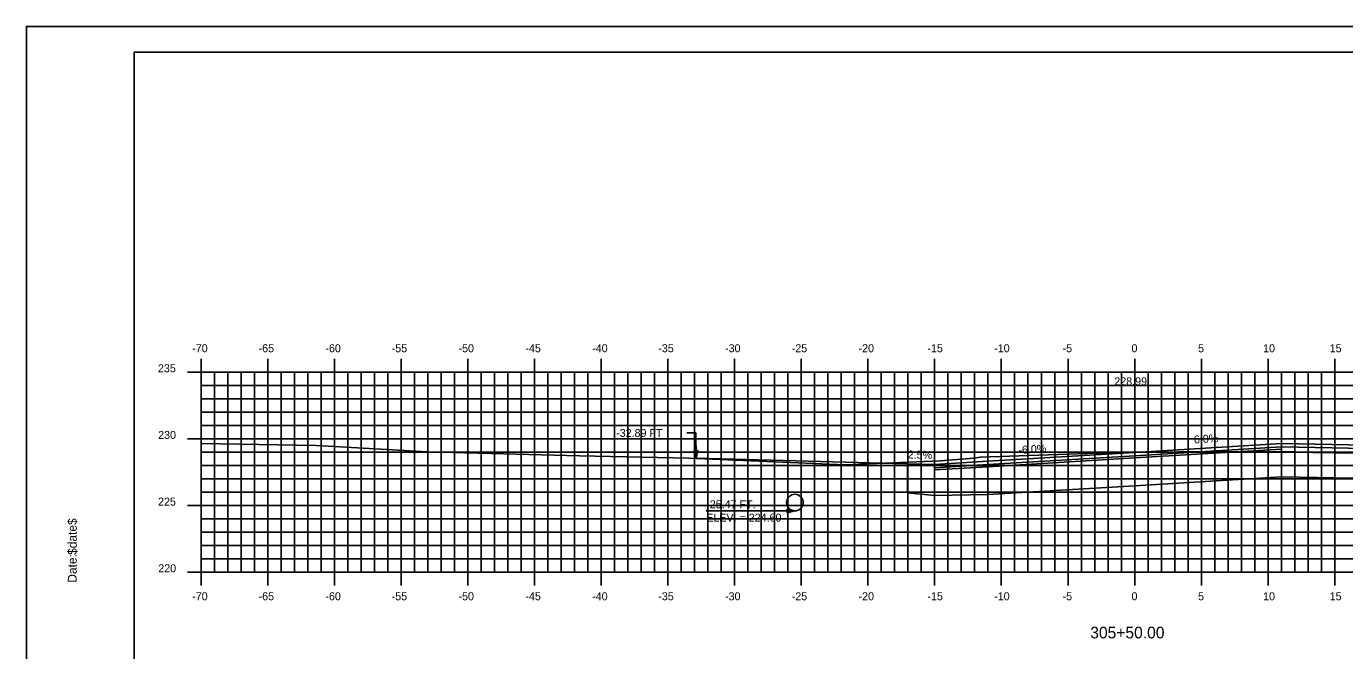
# Model space of a CAD drawing. Extents: x 1137211 to 1137381, y 608981 to 609091.
# Drawn here: x 1137210.8 to 1137309.6, y 609044.5 to 609091.3 of the extents above; entities that cross this region are included whole.
import ezdxf

# ---------------------------------------------------------------- set-up
doc = ezdxf.new("R2010")
doc.units = 0
for name, color, linetype in [('ANNOTATION', 7, 'Continuous'), ('BORDER', 7, 'Continuous'), ('D_Drainage_Culvert', 7, 'Continuous'), ('D_Roadway_Centerline', 7, 'Continuous'), ('D_Roadway_Centerline_Text', 7, 'Continuous'), ('D_Roadway_Edge_Shoulder', 7, 'Continuous'), ('D_Roadway_Edge_TW', 7, 'Continuous'), ('D_Roadway_Pavement', 7, 'Continuous'), ('D_Roadway_SubGrade', 7, 'Continuous'), ('D_Text_Standard', 7, 'Continuous'), ('H_V ANNOTATION', 7, 'Continuous'), ('MAJOR', 7, 'Continuous'), ('MINOR', 7, 'Continuous'), ('PLOT BOUNDARY', 7, 'Continuous'), ('S_Roadway_Centerline', 7, 'Continuous')]:
    doc.layers.add(name, color=color, linetype=linetype)

msp = doc.modelspace()

# ---------------------------------------------------------------- linework, layer by layer
at = {"layer": 'ANNOTATION'}
msp.add_line((1137276.858, 609058.474), (1137261.006, 609058.882), dxfattribs=at)
at = {"layer": 'BORDER'}
msp.add_lwpolyline([(1137218.897, 608984.335), (1137378.897, 608984.335), (1137378.897, 609089.335), (1137218.897, 609089.335)], close=True, dxfattribs=at)
at = {"layer": 'D_Drainage_Culvert'}
msp.add_circle((1137268.426, 609055.558), 0.625, dxfattribs=at)
at = {"layer": 'D_Roadway_Edge_Shoulder'}
for points in [[(1137304.896, 609059.983), (1137326.284, 609059.555), (1137326.284, 609059.305), (1137304.896, 609059.733)], [(1137282.896, 609058.663), (1137278.896, 609058.423), (1137278.896, 609058.173), (1137282.896, 609058.413)]]:
    msp.add_lwpolyline(points, close=True, dxfattribs=at)
at = {"layer": 'D_Roadway_Edge_TW'}
for points in [[(1137282.896, 609058.413), (1137282.896, 609058.663), (1137293.896, 609059.323), (1137304.896, 609059.983), (1137304.896, 609059.733), (1137293.896, 609059.073)], [(1137282.896, 609058.246), (1137278.896, 609058.006), (1137278.896, 609058.173), (1137282.896, 609058.413)]]:
    msp.add_lwpolyline(points, close=True, dxfattribs=at)
at = {"layer": 'D_Roadway_Pavement'}
msp.add_lwpolyline([(1137282.896, 609058.246), (1137282.896, 609058.413), (1137293.896, 609059.073), (1137304.896, 609059.733), (1137304.896, 609059.566), (1137293.896, 609058.906)], close=True, dxfattribs=at)
at = {"layer": 'D_Roadway_SubGrade'}
for points in [[(1137282.896, 609056.163), (1137282.896, 609058.246), (1137293.896, 609058.906), (1137304.896, 609059.566), (1137304.896, 609057.483), (1137293.896, 609056.823)], [(1137304.896, 609059.566), (1137304.896, 609059.733), (1137326.284, 609059.305), (1137326.284, 609059.555), (1137326.284, 609059.555), (1137335.681, 609056.925), (1137304.896, 609057.483)], [(1137276.858, 609056.289), (1137278.896, 609056.083), (1137282.896, 609056.163), (1137282.896, 609058.246), (1137282.896, 609058.413), (1137278.896, 609058.173), (1137278.896, 609058.423), (1137276.858, 609058.474)]]:
    msp.add_lwpolyline(points, close=True, dxfattribs=at)
at = {"layer": 'D_Text_Standard'}
msp.add_line((1137261.77, 609054.933), (1137266.367, 609054.933), dxfattribs=at)
for points in [[(1137261.006, 609058.882), (1137261.002, 609060.781), (1137260.322, 609060.781)], [(1137268.426, 609054.933), (1137267.047, 609054.933), (1137266.367, 609054.933)]]:
    msp.add_lwpolyline(points, dxfattribs=at)
for points in [[(1137261.006, 609058.882), (1137260.859, 609059.464), (1137261.15, 609059.464)], [(1137268.426, 609054.933), (1137267.844, 609054.787), (1137267.844, 609055.078)]]:
    msp.add_lwpolyline(points, close=True, dxfattribs=at)
at = {"layer": 'MAJOR'}
for p, q in [((1137223.896, 609066.337), (1137223.896, 609065.335)), ((1137228.896, 609066.337), (1137228.896, 609065.335)), ((1137233.896, 609066.337), (1137233.896, 609065.335)), ((1137238.896, 609066.337), (1137238.896, 609065.335)), ((1137243.896, 609066.337), (1137243.896, 609065.335)), ((1137248.896, 609066.337), (1137248.896, 609065.335)), ((1137253.896, 609066.337), (1137253.896, 609065.335)), ((1137258.896, 609066.337), (1137258.896, 609065.335)), ((1137263.896, 609066.337), (1137263.896, 609065.335)), ((1137268.896, 609066.337), (1137268.896, 609065.335)), ((1137273.896, 609066.337), (1137273.896, 609065.335)), ((1137278.896, 609066.337), (1137278.896, 609065.335)), ((1137283.896, 609066.337), (1137283.896, 609065.335)), ((1137288.896, 609066.337), (1137288.896, 609065.335)), ((1137293.896, 609066.337), (1137293.896, 609065.335)), ((1137298.896, 609066.337), (1137298.896, 609065.335)), ((1137303.896, 609066.337), (1137303.896, 609065.335)), ((1137308.896, 609066.337), (1137308.896, 609065.335)), ((1137222.894, 609065.335), (1137223.896, 609065.335)), ((1137223.896, 609065.335), (1137363.896, 609065.335)), ((1137223.896, 609050.335), (1137223.896, 609065.335)), ((1137223.896, 609050.335), (1137223.896, 609065.335)), ((1137223.896, 609065.335), (1137363.896, 609065.335)), ((1137228.896, 609050.335), (1137228.896, 609065.335)), ((1137233.896, 609050.335), (1137233.896, 609065.335)), ((1137238.896, 609050.335), (1137238.896, 609065.335)), ((1137243.896, 609050.335), (1137243.896, 609065.335)), ((1137248.896, 609050.335), (1137248.896, 609065.335)), ((1137253.896, 609050.335), (1137253.896, 609065.335)), ((1137258.896, 609050.335), (1137258.896, 609065.335)), ((1137263.896, 609050.335), (1137263.896, 609065.335)), ((1137268.896, 609050.335), (1137268.896, 609065.335)), ((1137273.896, 609050.335), (1137273.896, 609065.335)), ((1137278.896, 609050.335), (1137278.896, 609065.335)), ((1137283.896, 609050.335), (1137283.896, 609065.335)), ((1137288.896, 609050.335), (1137288.896, 609065.335)), ((1137293.896, 609050.335), (1137293.896, 609065.335)), ((1137298.896, 609050.335), (1137298.896, 609065.335)), ((1137303.896, 609050.335), (1137303.896, 609065.335)), ((1137308.896, 609050.335), (1137308.896, 609065.335)), ((1137222.894, 609060.335), (1137223.896, 609060.335)), ((1137223.896, 609060.335), (1137363.896, 609060.335)), ((1137222.894, 609055.335), (1137223.896, 609055.335)), ((1137223.896, 609055.335), (1137363.896, 609055.335)), ((1137222.894, 609050.335), (1137223.896, 609050.335)), ((1137223.896, 609050.335), (1137363.896, 609050.335)), ((1137223.896, 609050.335), (1137363.896, 609050.335)), ((1137223.896, 609049.333), (1137223.896, 609050.335)), ((1137228.896, 609049.333), (1137228.896, 609050.335)), ((1137233.896, 609049.333), (1137233.896, 609050.335)), ((1137238.896, 609049.333), (1137238.896, 609050.335)), ((1137243.896, 609049.333), (1137243.896, 609050.335)), ((1137248.896, 609049.333), (1137248.896, 609050.335)), ((1137253.896, 609049.333), (1137253.896, 609050.335)), ((1137258.896, 609049.333), (1137258.896, 609050.335)), ((1137263.896, 609049.333), (1137263.896, 609050.335)), ((1137268.896, 609049.333), (1137268.896, 609050.335)), ((1137273.896, 609049.333), (1137273.896, 609050.335)), ((1137278.896, 609049.333), (1137278.896, 609050.335)), ((1137283.896, 609049.333), (1137283.896, 609050.335)), ((1137288.896, 609049.333), (1137288.896, 609050.335)), ((1137293.896, 609049.333), (1137293.896, 609050.335)), ((1137298.896, 609049.333), (1137298.896, 609050.335)), ((1137303.896, 609049.333), (1137303.896, 609050.335)), ((1137308.896, 609049.333), (1137308.896, 609050.335))]:
    msp.add_line(p, q, dxfattribs=at)
at = {"layer": 'MINOR'}
for p, q in [((1137224.896, 609050.335), (1137224.896, 609065.335)), ((1137225.896, 609050.335), (1137225.896, 609065.335)), ((1137226.896, 609050.335), (1137226.896, 609065.335)), ((1137227.896, 609050.335), (1137227.896, 609065.335)), ((1137229.896, 609050.335), (1137229.896, 609065.335)), ((1137230.896, 609050.335), (1137230.896, 609065.335)), ((1137231.896, 609050.335), (1137231.896, 609065.335)), ((1137232.896, 609050.335), (1137232.896, 609065.335)), ((1137234.896, 609050.335), (1137234.896, 609065.335)), ((1137235.896, 609050.335), (1137235.896, 609065.335)), ((1137236.896, 609050.335), (1137236.896, 609065.335)), ((1137237.896, 609050.335), (1137237.896, 609065.335)), ((1137239.896, 609050.335), (1137239.896, 609065.335)), ((1137240.896, 609050.335), (1137240.896, 609065.335)), ((1137241.896, 609050.335), (1137241.896, 609065.335)), ((1137242.896, 609050.335), (1137242.896, 609065.335)), ((1137244.896, 609050.335), (1137244.896, 609065.335)), ((1137245.896, 609050.335), (1137245.896, 609065.335)), ((1137246.896, 609050.335), (1137246.896, 609065.335)), ((1137247.896, 609050.335), (1137247.896, 609065.335)), ((1137249.896, 609050.335), (1137249.896, 609065.335)), ((1137250.896, 609050.335), (1137250.896, 609065.335)), ((1137251.896, 609050.335), (1137251.896, 609065.335)), ((1137252.896, 609050.335), (1137252.896, 609065.335)), ((1137254.896, 609050.335), (1137254.896, 609065.335)), ((1137255.896, 609050.335), (1137255.896, 609065.335)), ((1137256.896, 609050.335), (1137256.896, 609065.335)), ((1137257.896, 609050.335), (1137257.896, 609065.335)), ((1137259.896, 609050.335), (1137259.896, 609065.335)), ((1137260.896, 609050.335), (1137260.896, 609065.335)), ((1137261.896, 609050.335), (1137261.896, 609065.335)), ((1137262.896, 609050.335), (1137262.896, 609065.335)), ((1137264.896, 609050.335), (1137264.896, 609065.335)), ((1137265.896, 609050.335), (1137265.896, 609065.335)), ((1137266.896, 609050.335), (1137266.896, 609065.335)), ((1137267.896, 609050.335), (1137267.896, 609065.335)), ((1137269.896, 609050.335), (1137269.896, 609065.335)), ((1137270.896, 609050.335), (1137270.896, 609065.335)), ((1137271.896, 609050.335), (1137271.896, 609065.335)), ((1137272.896, 609050.335), (1137272.896, 609065.335)), ((1137274.896, 609050.335), (1137274.896, 609065.335)), ((1137275.896, 609050.335), (1137275.896, 609065.335)), ((1137276.896, 609050.335), (1137276.896, 609065.335)), ((1137277.896, 609050.335), (1137277.896, 609065.335)), ((1137279.896, 609050.335), (1137279.896, 609065.335)), ((1137280.896, 609050.335), (1137280.896, 609065.335)), ((1137281.896, 609050.335), (1137281.896, 609065.335)), ((1137282.896, 609050.335), (1137282.896, 609065.335)), ((1137284.896, 609050.335), (1137284.896, 609065.335)), ((1137285.896, 609050.335), (1137285.896, 609065.335)), ((1137286.896, 609050.335), (1137286.896, 609065.335)), ((1137287.896, 609050.335), (1137287.896, 609065.335)), ((1137289.896, 609050.335), (1137289.896, 609065.335)), ((1137290.896, 609050.335), (1137290.896, 609065.335)), ((1137291.896, 609050.335), (1137291.896, 609065.335)), ((1137292.896, 609050.335), (1137292.896, 609065.335)), ((1137294.896, 609050.335), (1137294.896, 609065.335)), ((1137295.896, 609050.335), (1137295.896, 609065.335)), ((1137296.896, 609050.335), (1137296.896, 609065.335)), ((1137297.896, 609050.335), (1137297.896, 609065.335)), ((1137299.896, 609050.335), (1137299.896, 609065.335)), ((1137300.896, 609050.335), (1137300.896, 609065.335)), ((1137301.896, 609050.335), (1137301.896, 609065.335)), ((1137302.896, 609050.335), (1137302.896, 609065.335)), ((1137304.896, 609050.335), (1137304.896, 609065.335)), ((1137305.896, 609050.335), (1137305.896, 609065.335)), ((1137306.896, 609050.335), (1137306.896, 609065.335)), ((1137307.896, 609050.335), (1137307.896, 609065.335)), ((1137223.896, 609064.335), (1137363.896, 609064.335)), ((1137223.896, 609064.335), (1137224.898, 609064.335)), ((1137223.896, 609063.335), (1137363.896, 609063.335)), ((1137223.896, 609063.335), (1137224.898, 609063.335)), ((1137223.896, 609062.335), (1137363.896, 609062.335)), ((1137223.896, 609062.335), (1137224.898, 609062.335)), ((1137223.896, 609061.335), (1137363.896, 609061.335)), ((1137223.896, 609061.335), (1137224.898, 609061.335)), ((1137223.896, 609059.335), (1137363.896, 609059.335)), ((1137223.896, 609059.335), (1137224.898, 609059.335)), ((1137223.896, 609058.335), (1137363.896, 609058.335)), ((1137223.896, 609058.335), (1137224.898, 609058.335)), ((1137223.896, 609057.335), (1137363.896, 609057.335)), ((1137223.896, 609057.335), (1137224.898, 609057.335)), ((1137223.896, 609056.335), (1137363.896, 609056.335)), ((1137223.896, 609056.335), (1137224.898, 609056.335)), ((1137223.896, 609054.335), (1137363.896, 609054.335)), ((1137223.896, 609054.335), (1137224.898, 609054.335)), ((1137223.896, 609053.335), (1137363.896, 609053.335)), ((1137223.896, 609053.335), (1137224.898, 609053.335)), ((1137223.896, 609052.335), (1137363.896, 609052.335)), ((1137223.896, 609052.335), (1137224.898, 609052.335)), ((1137223.896, 609051.335), (1137363.896, 609051.335)), ((1137223.896, 609051.335), (1137224.898, 609051.335))]:
    msp.add_line(p, q, dxfattribs=at)
at = {"layer": 'PLOT BOUNDARY'}
msp.add_lwpolyline([(1137210.803, 608981.276), (1137380.803, 608981.276), (1137380.803, 609091.276), (1137210.803, 609091.276)], close=True, dxfattribs=at)
at = {"layer": 'S_Roadway_Centerline'}
msp.add_lwpolyline([(1137223.896, 609059.991), (1137232.566, 609059.835), (1137240.871, 609059.374), (1137252.276, 609059.07), (1137260.477, 609058.905), (1137272.159, 609058.383), (1137279.336, 609058.701), (1137281.863, 609058.904), (1137282.301, 609058.967), (1137290.35, 609059.243), (1137293.067, 609059.328), (1137296.178, 609059.337), (1137297.212, 609059.356), (1137303.521, 609059.383), (1137305.962, 609059.371), (1137307.256, 609059.316), (1137308.838, 609059.302), (1137312.741, 609059.235)], dxfattribs=at)

# ---------------------------------------------------------------- texts
at = {"layer": 'ANNOTATION'}
for s, rotation, p in [('6.0%', 3.43363, (1137298.354, 609059.992)), ('2.5%', 358.5679, (1137276.875, 609058.874)), ('-6.0%', 3.43363, (1137285.193, 609059.202))]:
    msp.add_text(s, height=0.6, rotation=rotation, dxfattribs=at).set_placement(p)
at = {"layer": 'BORDER'}
for s, p in [('$date$', (1137214.581, 609051.64)), ('Date:', (1137214.581, 609049.552))]:
    msp.add_text(s, height=0.6696, rotation=90, dxfattribs=at).set_placement(p)
at = {"layer": 'D_Roadway_Centerline'}
for s, p in [('C', (1137293.891, 609059.323)), ('L', (1137293.896, 609059.315))]:
    msp.add_text(s, height=0.0146, dxfattribs=at).set_placement(p)
at = {"layer": 'D_Roadway_Centerline_Text'}
msp.add_text('228.99', height=0.6, dxfattribs=at).set_placement((1137292.366, 609064.355))
at = {"layer": 'D_Text_Standard'}
for s, p in [('-32.89 FT', (1137255.017, 609060.481)), ('-25.47 FT.', (1137261.77, 609055.133)), ('ELEV. = 224.60', (1137261.77, 609054.133))]:
    msp.add_text(s, height=0.6, dxfattribs=at).set_placement(p)
at = {"layer": 'H_V ANNOTATION'}
for s, height, p in [('-70', 0.6, (1137223.238, 609066.835)), ('-65', 0.6, (1137228.214, 609066.835)), ('-60', 0.6, (1137233.222, 609066.835)), ('-55', 0.6, (1137238.192, 609066.835)), ('-50', 0.6, (1137243.2, 609066.835)), ('-45', 0.6, (1137248.214, 609066.835)), ('-40', 0.6, (1137253.222, 609066.835)), ('-35', 0.6, (1137258.176, 609066.835)), ('-30', 0.6, (1137263.185, 609066.835)), ('-25', 0.6, (1137268.182, 609066.835)), ('-20', 0.6, (1137273.19, 609066.835)), ('-15', 0.6, (1137278.353, 609066.835)), ('-10', 0.6, (1137283.361, 609066.835)), ('-5', 0.6, (1137288.487, 609066.835)), ('0', 0.6, (1137293.655, 609066.835)), ('5', 0.6, (1137298.647, 609066.835)), ('10', 0.6, (1137303.522, 609066.835)), ('15', 0.6, (1137308.514, 609066.835)), ('235', 0.6, (1137220.667, 609065.335)), ('230', 0.6, (1137220.683, 609060.335)), ('225', 0.6, (1137220.678, 609055.335)), ('220', 0.6, (1137220.694, 609050.335)), ('-70', 0.6, (1137223.238, 609048.235)), ('-65', 0.6, (1137228.214, 609048.235)), ('-60', 0.6, (1137233.222, 609048.235)), ('-55', 0.6, (1137238.192, 609048.235)), ('-50', 0.6, (1137243.2, 609048.235)), ('-45', 0.6, (1137248.214, 609048.235)), ('-40', 0.6, (1137253.222, 609048.235)), ('-35', 0.6, (1137258.176, 609048.235)), ('-30', 0.6, (1137263.185, 609048.235)), ('-25', 0.6, (1137268.182, 609048.235)), ('-20', 0.6, (1137273.19, 609048.235)), ('-15', 0.6, (1137278.353, 609048.235)), ('-10', 0.6, (1137283.361, 609048.235)), ('-5', 0.6, (1137288.487, 609048.235)), ('0', 0.6, (1137293.655, 609048.235)), ('5', 0.6, (1137298.647, 609048.235)), ('10', 0.6, (1137303.522, 609048.235)), ('15', 0.6, (1137308.514, 609048.235)), ('305+50.00', 0.875, (1137290.564, 609045.378))]:
    msp.add_text(s, height=height, dxfattribs=at).set_placement(p)
at = {"layer": 'MAJOR'}
msp.add_text('-', height=0.006, dxfattribs=at).set_placement((1137223.892, 609050.335))
at = {"layer": 'S_Roadway_Centerline'}
for s, p in [('L', (1137293.059, 609059.321)), ('C', (1137293.062, 609059.328))]:
    msp.add_text(s, height=0.0146, dxfattribs=at).set_placement(p)

doc.saveas('drawing.dxf')
